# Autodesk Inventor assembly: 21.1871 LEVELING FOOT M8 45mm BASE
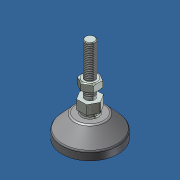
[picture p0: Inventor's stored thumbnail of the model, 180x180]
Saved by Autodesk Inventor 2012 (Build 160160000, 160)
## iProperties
Created: 2007-03
Part Number: 21.1871 LEVELING FOOT M8 45mm BASE
Document SubType Name: Assembly
Designer: Andy Moles
Author: Andy Moles
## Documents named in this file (5)
- C:\Andys Backup Data\ANDY'S INVENTOR\INVENTOR LIBRARIES\PARTS LIBRARY\FEET WHEELS FLOOR FASTENING SUPPORTS\21.1871 LEVELING FOOT M8 45mm BASE.iam
- C:\Andys Backup Data\ANDY'S INVENTOR\INVENTOR LIBRARIES\PARTS LIBRARY\FEET WHEELS FLOOR FASTENING SUPPORTS\SUBCOMPONENTS\LEVELING FEET SUBCOMPONENTS\ANTI-SKID PAD 45mm.ipt
- C:\Andys Backup Data\ANDY'S INVENTOR\INVENTOR LIBRARIES\PARTS LIBRARY\FEET WHEELS FLOOR FASTENING SUPPORTS\SUBCOMPONENTS\LEVELING FEET SUBCOMPONENTS\PAD 45mm PLASTIC.ipt
- C:\Andys Backup Data\ANDY'S INVENTOR\INVENTOR LIBRARIES\PARTS LIBRARY\FEET WHEELS FLOOR FASTENING SUPPORTS\SUBCOMPONENTS\LEVELING FEET SUBCOMPONENTS\THREADED STUD 8mm.ipt
- C:\Andys Backup Data\ANDY'S INVENTOR\INVENTOR LIBRARIES\PARTS LIBRARY\FASTENING ELEMENTS\NUTS\21.1526 M8 HEX NUT.ipt
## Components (4 placed, 4 different names)
1. ANTI-SKID PAD 45mm:1 — Insert:1
2. PAD 45mm PLASTIC:1 — Insert:1, Tangent:1, Mate:1
3. THREADED STUD 8mm:1 — Tangent:1, Mate:1, Mate:2
4. 21.1526 M8 HEX NUT:1 — Mate:2
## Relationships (4: Mate 2, Insert 1, Tangent 1)
- Insert:1: ANTI-SKID PAD 45mm:1 ↔ PAD 45mm PLASTIC:1
- Tangent:1: PAD 45mm PLASTIC:1 ↔ THREADED STUD 8mm:1
- Mate:1: PAD 45mm PLASTIC:1 ↔ THREADED STUD 8mm:1
- Mate:2: THREADED STUD 8mm:1 ↔ 21.1526 M8 HEX NUT:1
